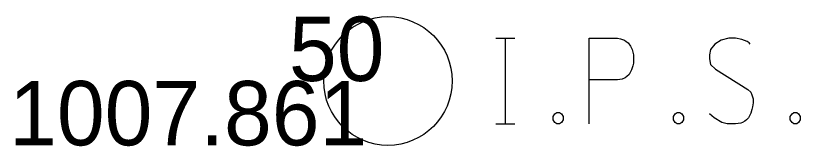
# Model space of a CAD drawing. Extents: x 2354693 to 2355622, y 637071 to 710080.
# Drawn here: x 2355036.83 to 2355051.5, y 709726.15 to 709728.58 of the extents above; entities that cross this region are included whole.
import ezdxf

# ---------------------------------------------------------------- set-up
doc = ezdxf.new("R2010")
doc.units = 0
for name, color, linetype in [('SV_P_Mon_Cells_Set', 7, 'Continuous'), ('SV_X_Text_Elevation', 7, 'Continuous'), ('SV_X_Text_Name', 7, 'Continuous')]:
    doc.layers.add(name, color=color, linetype=linetype)

msp = doc.modelspace()

# ---------------------------------------------------------------- linework, layer by layer
at = {"layer": 'SV_P_Mon_Cells_Set'}
for points in [[(2355045.809, 709728.164), (2355046.162, 709728.164)], [(2355045.985, 709726.564), (2355045.985, 709728.164)], [(2355047.551, 709726.564), (2355047.551, 709728.164), (2355048.08, 709728.164), (2355048.135, 709728.151), (2355048.212, 709728.126), (2355048.245, 709728.101), (2355048.278, 709728.076), (2355048.322, 709728.013), (2355048.355, 709727.95), (2355048.377, 709727.849), (2355048.377, 709727.698), (2355048.366, 709727.648), (2355048.344, 709727.572), (2355048.3, 709727.484), (2355048.256, 709727.446), (2355048.223, 709727.421), (2355048.168, 709727.396), (2355048.08, 709727.383), (2355047.551, 709727.383)], [(2355050.56, 709728.051), (2355050.538, 709728.076), (2355050.505, 709728.101), (2355050.406, 709728.139), (2355050.284, 709728.164), (2355050.196, 709728.164), (2355050.163, 709728.164), (2355050.02, 709728.126), (2355049.899, 709728.051), (2355049.821, 709727.95), (2355049.799, 709727.849), (2355049.799, 709727.774), (2355049.821, 709727.673), (2355049.91, 709727.585), (2355050.516, 709727.207), (2355050.571, 709727.156), (2355050.593, 709727.106), (2355050.615, 709727.03), (2355050.615, 709726.955), (2355050.604, 709726.879), (2355050.593, 709726.829), (2355050.571, 709726.766), (2355050.549, 709726.715), (2355050.527, 709726.678), (2355050.494, 709726.64), (2355050.461, 709726.615), (2355050.417, 709726.589), (2355050.384, 709726.577), (2355050.284, 709726.564), (2355050.13, 709726.564), (2355050.031, 709726.589), (2355049.887, 709726.678), (2355049.799, 709726.753)], [(2355046.944, 709726.778), (2355046.999, 709726.778), (2355047.033, 709726.753), (2355047.066, 709726.703), (2355047.066, 709726.64), (2355047.033, 709726.589), (2355046.999, 709726.564), (2355046.944, 709726.564), (2355046.911, 709726.589), (2355046.878, 709726.64), (2355046.878, 709726.703), (2355046.911, 709726.753), (2355046.944, 709726.778)], [(2355049.193, 709726.778), (2355049.248, 709726.778), (2355049.281, 709726.753), (2355049.314, 709726.703), (2355049.314, 709726.64), (2355049.281, 709726.589), (2355049.248, 709726.564), (2355049.193, 709726.564), (2355049.16, 709726.589), (2355049.127, 709726.64), (2355049.127, 709726.703), (2355049.16, 709726.753), (2355049.193, 709726.778)], [(2355051.376, 709726.778), (2355051.431, 709726.778), (2355051.464, 709726.753), (2355051.497, 709726.703), (2355051.497, 709726.64), (2355051.464, 709726.589), (2355051.431, 709726.564), (2355051.376, 709726.564), (2355051.342, 709726.589), (2355051.31, 709726.64), (2355051.31, 709726.703), (2355051.342, 709726.753), (2355051.376, 709726.778)], [(2355045.809, 709726.564), (2355046.162, 709726.564)]]:
    msp.add_lwpolyline(points, dxfattribs=at)
msp.add_circle((2355043.79, 709727.363), 1.2, dxfattribs=at)

# ---------------------------------------------------------------- texts
at = {"layer": 'SV_X_Text_Elevation'}
msp.add_text('1007.861', height=1.2, dxfattribs=at).set_placement((2355036.711, 709726.163))
at = {"layer": 'SV_X_Text_Name'}
msp.add_text('50', height=1.2, dxfattribs=at).set_placement((2355041.94, 709727.363))

doc.saveas('drawing.dxf')
